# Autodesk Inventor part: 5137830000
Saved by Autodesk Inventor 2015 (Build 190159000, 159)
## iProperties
Created: 2020-07
Part Number: 5137830000
Checked By: TraceParts S.A.
Material: Generic
Catalog Web Link: www.traceparts.com
Document SubType Name: Modeling
Designer: TraceParts
Density: 1 g/cm^3
Appearance: Default
Company: TraceParts S.A.
Author: TraceParts
REFERENCE: 5137830000
DESIGN: CVAB-6000/450 N ECOWATT 1,0KW (230V 50/60HZ) - 5137830000
SUPPLIER: Soler & Palau
TraceParts.PartNumber: 10-20122018-119636
TraceParts.PartTitle: CVAB/T-N_ECO
TraceParts.InstanceId: 10-20122018-1196367PLNA3UX5YIYSHKZJATCZ639Y
TraceParts.PartStatus: Published
TraceParts.PartVersion: 1.0.2
TRACEPARTS: TRACEPARTS
TraceParts.PartLanguage: en
TraceParts.ClassPath: SOLER_PALAU:10-20122018-119636
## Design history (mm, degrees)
feature "5137830000"
body "Solid1"
